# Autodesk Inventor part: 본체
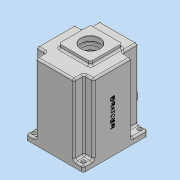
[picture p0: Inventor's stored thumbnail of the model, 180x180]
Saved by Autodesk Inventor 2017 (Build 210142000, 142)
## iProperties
Part Number: 본체
Material: 일반
Document SubType Name: Modeling
Designer: MRC
Density: 1 g/cm^3
Appearance: 기본값
Mass: 520.091 g
Surface Area: 1170.8 cm^2
Volume: 520.091 cm^3
Author: MRC
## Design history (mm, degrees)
sketch "스케치1"
  geometry: L1 (-49, 60)-(49, 60); L2 (49, 60)-(49, -50); L3 (49, -50)-(-49, -50); L4 (-49, -50)-(-49, 60); 2 further points
  constraints: 8 end point, 2 parallel, 1 horizontal, 1 midpoint, 1 perpendicular, 1 vertical alignment
  dimensions: "d0" = 98 distance of L1.start L1.end; "d45" = 50 distance from line of L3 point (0, 0); "d46" = 110 distance of L3.end L1.start
extrude "돌출1" new body sketch "스케치1" stored distance "d2" = 130; taper "d3" = 0 deg
sketch "스케치2"
  geometry: L1 (49, 60)-(-49, 60) reference; L2 (-49, 60)-(-49, -50) reference; L3 (49, -50)-(49, 60) reference; L4 (-49, -50)-(49, -50) reference; L5 (-33, 60)-(-33, 33); L6 (-33, 33)-(-49, 33); L7 (33, -33)-(49, -33); L8 (33, 33)-(49, 33); L9 (33, 33)-(33, 60); L10 (33, -33)-(33, -50); L11 (-49, -33)-(-33, -33); L12 (-33, -33)-(-33, -50); 1 further point
  constraints: 16 end point, 8 point on line, 3 equal length, 3 vertical, 2 horizontal, 2 perpendicular, 1 horizontal alignment
  dimensions: "d4" = 27 distance of L5.start L5.end; "d5" = 16 distance of L5.end L6.end; "d39" = 17 distance of L7.start L10.end; "d42" = 16 distance of L11.start L11.end; "d43" = 17 distance of L11.end L12.end
extrude "돌출2" cut sketch "스케치2" distance "d6" = 120; taper "d7" = 0 deg
sketch "스케치3"
  geometry: L1 (27, -16)-(-27, -16); L2 (-27, -16)-(-27, 38); L3 (-27, 38)-(27, 38); L4 (27, 38)-(27, -16); L5 (27, -16)-(-27, 38); L6 (-27, -16)-(27, 38); 7 further points; 1 other entity
  constraints: 12 end point, 3 midpoint, 2 parallel, 1 horizontal, 1 perpendicular, 1 vertical alignment, 1 other
  dimensions: "d9" = 61 dimension on point (0, 11); "d10" = 54 distance of L2.end L3.end; "d11" = 54 distance of L1.end L2.end
extrude "돌출3" join sketch "스케치3" distance "d12" = 7; taper "d13" = 0 deg
sketch "스케치4"
  geometry: L1 (0, 0)-(98, 0) reference; C1 r 22.5 at (49, -40); C2 r 15 at (49, -89); 1 further point
  constraints: 2 centre point, 2 vertical alignment
  dimensions: "d14" = 30 diameter of C2; "d15" = 45 diameter of C1; "d16" = 40 distance from line of L1 C1.centre; "d17" = 49 distance of C2.centre C1.centre
extrude "돌출4" join sketch "스케치4" distance "d18" = 5; taper "d19" = 0 deg
extrude "돌출5" join sketch "스케치4" distance "d20" = 10; taper "d21" = 0 deg
fillet "모깎기1" dims "d27" = 3
sketch "스케치7"
  geometry: L1 (-46, -50)-(46, -50) reference; L2 (-23, 50)-(-23, 35.143); L3 (23, 50)-(23, 35.143); L4 (23, 50)-(-23, 50); L5 (26, 36.729)-(26, 53); L6 (26, 53)-(-26, 53); L7 (-26, 53)-(-26, 36.729); A1 r 42 centre (0, 0) between (-23, 35.143) and (23, 35.143); A2 r 45 centre (0, 0) between (-26, 36.729) and (26, 36.729); 1 further point
  constraints: 12 end point, 4 point on circle, 2 centre point, 2 vertical, 1 coincident, 1 horizontal, 3 other
  dimensions: "d28" = 50 distance from line of L1 A1.centre; "d29" = 84 diameter of A1; "d30" = 46 distance of L3.start L2.start; "d31" = 50 distance from line of A1.centre L4; "d32" = 23 distance from line of L3 point (0, 0); "d33" = 3 radial gap between concentric circles of A1 A2
extrude "돌출7" cut sketch "스케치7" distance "d34" = 9; taper "d35" = 0 deg
sketch "스케치8"
  geometry: L1 (-26, 53)-(26, 53) reference; L2 (-26, 36.729)-(-26, 53) reference; L3 (26, 53)-(26, 36.729) reference; L4 (23, 50)-(-23, 50); L5 (-23, 50)-(-23, 35.143); L6 (23, 35.143)-(23, 50); A1 r 45 centre (0, 0) between (-26, 36.729) and (26, 36.729) reference; A2 r 42 centre (0, 0) between (-23, 35.143) and (23, 35.143); 1 further point
  constraints: 6 end point, 2 point on circle, 1 centre point, 3 other
  dimensions: "d36" = 3 distance between parallel lines of L1 L4
extrude "돌출8" cut sketch "스케치8" distance "d37" = 112; taper "d38" = 0 deg
sketch "스케치9"
  geometry: A1 r 21 centre (0, 11) between (8.978, -7.984) and (-8.978, -7.984); A2 r 15 centre (0, -20) between (-8.978, -7.984) and (8.978, -7.984); 1 further point
  constraints: 4 point on circle, 2 centre point, 2 vertical alignment
  dimensions: "d47" = 42 diameter of A1; "d48" = 30 diameter of A2; "d51" = 11 distance of A1.centre point (0, 0); "d52" = 20 distance of point (0, 0) A2.centre
fillet "모깎기3" dims "d49" = 6
fillet "모깎기4" dims "d50" = 3
extrude "돌출9" join sketch "스케치9" distance "d53" = 7; taper "d54" = 0 deg
sketch "스케치11"
  geometry: C1 r 11 at (0, -20); A1 r 15 centre (0, -20) between (-8.978, -7.984) and (8.978, -7.984) reference; 1 further point
  constraints: 1 centre point, 1 concentric
  dimensions: "d55" = 22 diameter of C1
extrude "돌출10" cut sketch "스케치11" distance "d56" = 7; taper "d57" = 0 deg
sketch "스케치12"
  geometry: C1 r 9.5 at (0, 0); C2 r 11 at (0, 0) reference; 1 further point
  constraints: 1 centre point, 1 concentric
  dimensions: "d58" = 19 diameter of C1
extrude "돌출11" cut sketch "스케치12" distance "d59" = 3; taper "d60" = 0 deg
sketch "스케치13"
  geometry: C1 r 17.5 at (0, 11); A1 r 21 centre (0, 11) between (8.978, -7.984) and (-8.978, -7.984) reference; 1 further point
  constraints: 1 centre point, 1 concentric
  dimensions: "d61" = 35 diameter of C1
extrude "돌출12" cut sketch "스케치13" distance "d62" = 10; taper "d63" = 0 deg
sketch "스케치16"
  geometry: C1 r 16 at (0, 11); 1 further point
  constraints: 1 centre point, 1 vertical alignment
  dimensions: "d65" = 32 diameter of C1; "d66" = 11 distance of point (0, 0) C1.centre
extrude "돌출13" cut sketch "스케치16" distance "d67" = 8.3; taper "d68" = 0 deg
sketch "스케치17"
  geometry: C1 r 14 at (0, 0); 1 further point
  constraints: 1 centre point, 1 vertical alignment
  dimensions: "d69" = 11 distance of point (0, -11) C1.centre; "d70" = 28 diameter of C1
extrude "돌출14" cut sketch "스케치17" stored distance "d71" = 8.3; taper "d72" = 0 deg
sketch "스케치18"
  geometry: C1 r 10 at (0, 0); C2 r 15 at (0, 0) reference; 1 further point
  constraints: 1 centre point, 1 concentric
  dimensions: "d73" = 20 diameter of C1
extrude "돌출15" cut sketch "스케치18" distance "d74" = 10; taper "d75" = 0 deg
sketch "스케치19"
  geometry: C1 r 15 at (0, 0); C2 r 10 at (0, 0) reference; 1 further point
  constraints: 1 centre point, 1 concentric
  dimensions: "d76" = 30 diameter of C1
extrude "돌출16" cut sketch "스케치19" distance "d77" = 5; taper "d78" = 0 deg
hole "구멍1" diameter "d81" = 33.376; stored, may be unused: countersink angle "d85" = 90 deg, drill point angle "d87" = 0 deg; dims "d79" = 10, "d80" = 10, "d82" = 70, "d83" = 4, "d84" = 2, "d86" = 77.3
sketch "스케치20"
  geometry: L1 (42, -43)-(-42, -43); L2 (-42, -43)-(-42, 53); L3 (-42, 53)-(42, 53); L4 (42, 53)-(42, -43); L5 (46, 60)-(-46, 60) reference; L6 (-49, 57)-(-49, -47) reference; L7 (-46, -50)-(46, -50) reference; C1 r 3.5 at (-42, 53); C2 r 3.5 at (42, 53); C3 r 3.5 at (42, -43); C4 r 3.5 at (-42, -43); 2 further points
  constraints: 8 end point, 4 centre point, 4 coincident, 2 parallel, 1 equal radius, 1 horizontal, 1 midpoint, 1 perpendicular, 1 vertical alignment
  dimensions: "d88" = 7 distance between parallel lines of L5 L3; "d89" = 7 distance between parallel lines of L6 L2; "d90" = 7 distance between parallel lines of L7 L1; "d91" = 7 diameter of C1; "d92" = 7 diameter of C2; "d93" = 7 diameter of C4
extrude "돌출17" cut sketch "스케치20" stored distance "d94" = 5; taper "d95" = 0 deg
sketch "스케치21"
  geometry: L1 (-36, 4)-(-41.809, 4); L2 (-36, -4)-(-41.809, -4); L3 (36, 4)-(41.809, 4); L4 (36, -4)-(41.809, -4); A1 r 4 centre (-36, 0) between (-36, -4) and (-36, 4); A2 r 4 centre (36, 0) between (36, 4) and (36, -4); A3 r 42 centre (0, 0) between (-25.375, 33.468) and (25.375, 33.468) reference; 1 further point
  constraints: 8 end point, 8 point on circle, 4 horizontal, 4 tangent, 2 centre point, 2 horizontal alignment, 1 equal radius
  dimensions: "d96" = 72 distance of A1.centre A2.centre; "d97" = 36 distance of point (0, 0) A2.centre; "d98" = 8 diameter of A1
extrude "돌출18" join sketch "스케치21" stored distance "d99" = 5; taper "d100" = 0 deg
hole "구멍2" diameter "d103" = 3.242; stored, may be unused: countersink angle "d107" = 90 deg, drill point angle "d109" = 118 deg; dims "d101" = 10, "d102" = 10, "d104" = 7, "d105" = 4, "d106" = 2, "d108" = 9
hole "구멍3" diameter "d112" = 3.242; stored, may be unused: countersink angle "d116" = 90 deg, drill point angle "d118" = 118 deg; dims "d110" = 10, "d111" = 10, "d113" = 7, "d114" = 4, "d115" = 2, "d117" = 9
fillet "모깎기5" dims "d119" = 3
fillet "모깎기6" dims "d120" = 3
fillet "모깎기7" dims "d121" = 3
fillet "모깎기8" dims "d122" = 3
fillet "모깎기9" dims "d123" = 3
fillet "모깎기10" dims "d124" = 0.3
fillet "모깎기11" dims "d125" = 0.3
chamfer "모따기1" distance "d126" = 0.8; stored, may be unused: second distance "d127" = 2, angle "d128" = 30 deg
fillet "모깎기12" dims "d129" = 3
fillet "모깎기13" dims "d130" = 3
fillet "모깎기14" dims "d131" = 3
fillet "모깎기15" dims "d132" = 3
fillet "모깎기16" dims "d133" = 3
fillet "모깎기17" dims "d134" = 3
fillet "모깎기18" dims "d135" = 3
sketch "스케치22"
  geometry: L1 (-130, 104)-(-130, 83) reference; L2 (-13, 80)-(-127, 80) reference; 2 further points
  constraints: 1 other
  dimensions: "d136" = 65 distance from line of L1 point (-65, 47); "d137" = 33 distance from line of point (-65, 47) L2
feature "엠보싱1" sketch "스케치22" dims "d4" = 27, "d5" = 16, "d39" = 17, "d138" = 0.5, "d139" = 0
chamfer "모따기2" distance "d140" = 1; stored, may be unused: second distance "d141" = 2, angle "d142" = 30 deg
chamfer "모따기3" distance "d143" = 1; stored, may be unused: second distance "d144" = 2, angle "d145" = 30 deg
fillet "모깎기19" dims "d146" = 0.3
node "솔리드1"
